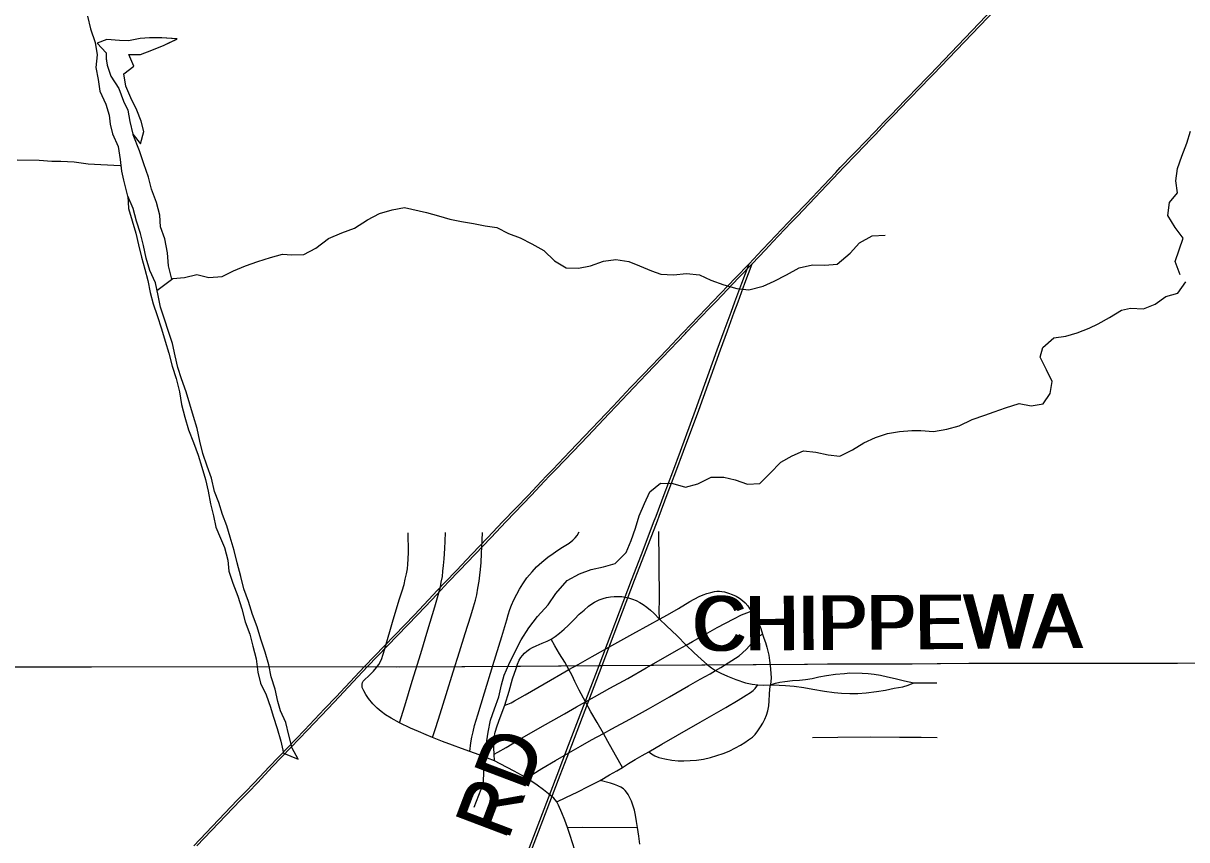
# Model space of a CAD drawing. Extents: x 0 to 34, y 0 to 22.
# Drawn here: x 21.074 to 22.288, y 9.409 to 10.261 of the extents above; entities that cross this region are included whole.
import ezdxf

# ---------------------------------------------------------------- set-up
doc = ezdxf.new("R2010")
doc.units = 0
for name, color, linetype in [('GM_X_City_Street', 7, 'Continuous'), ('GM_X_County_Road', 7, 'Continuous'), ('GM_X_County_Road_Text', 7, 'Continuous'), ('GM_X_Minor_Lake', 7, 'Continuous'), ('GM_X_Minor_River', 7, 'Continuous'), ('GM_X_US_Route', 7, 'Continuous')]:
    doc.layers.add(name, color=color, linetype=linetype)

msp = doc.modelspace()

# ---------------------------------------------------------------- linework, layer by layer
at = {"layer": 'GM_X_City_Street'}
for points in [[(21.4275, 9.5716), (21.4279, 9.5733), (21.4288, 9.5746), (21.4302, 9.5761), (21.4347, 9.5801), (21.4395, 9.585), (21.4427, 9.5888), (21.4452, 9.5921), (21.4478, 9.5971), (21.4497, 9.6028), (21.4519, 9.6107), (21.4594, 9.6362), (21.4663, 9.6593), (21.4693, 9.6688), (21.4713, 9.6755), (21.4726, 9.681), (21.4739, 9.6865), (21.4748, 9.6917), (21.4753, 9.6966), (21.4756, 9.702), (21.4758, 9.709), (21.4757, 9.7294)], [(21.4666, 9.5312), (21.472, 9.5487), (21.4799, 9.5744), (21.4889, 9.6034), (21.4963, 9.6282), (21.5034, 9.6521), (21.5068, 9.6642), (21.5092, 9.6729), (21.5102, 9.6778), (21.5113, 9.6837), (21.5119, 9.6894), (21.5125, 9.6951), (21.5132, 9.7021), (21.5139, 9.7129), (21.5142, 9.7205), (21.5144, 9.7296)], [(21.5011, 9.5159), (21.5044, 9.5264), (21.5089, 9.5406), (21.5151, 9.5605), (21.5226, 9.5844), (21.5292, 9.6053), (21.535, 9.6242), (21.5411, 9.6429), (21.5439, 9.6522), (21.5458, 9.659), (21.5471, 9.6648), (21.5484, 9.6716), (21.5496, 9.6789), (21.5505, 9.6852), (21.5511, 9.6911), (21.5517, 9.6982), (21.5522, 9.7076), (21.5528, 9.7216), (21.553, 9.7298)], [(21.5401, 9.5013), (21.5411, 9.5101), (21.5421, 9.5161), (21.5433, 9.5217), (21.5448, 9.5282), (21.5483, 9.5396), (21.5553, 9.5623), (21.564, 9.5909), (21.5733, 9.6212), (21.5784, 9.6385), (21.58, 9.6438), (21.5817, 9.6492), (21.5835, 9.6538), (21.5858, 9.6593), (21.5888, 9.6654), (21.5917, 9.6705), (21.5952, 9.676), (21.5995, 9.6823), (21.6048, 9.6887), (21.6096, 9.6937), (21.6149, 9.6988), (21.6212, 9.7038), (21.6269, 9.7079), (21.6316, 9.7111), (21.6367, 9.7143), (21.6436, 9.7187), (21.6472, 9.7216), (21.6497, 9.7241), (21.6518, 9.7267), (21.6541, 9.7302)], [(21.7377, 9.6394), (21.7375, 9.6488), (21.7376, 9.6585), (21.7375, 9.6989), (21.737, 9.7306)], [(21.5764, 9.5495), (21.5797, 9.5507), (21.5829, 9.5521), (21.5865, 9.5539), (21.5977, 9.5603), (21.6109, 9.568), (21.6239, 9.5756), (21.6349, 9.5819), (21.6432, 9.5866), (21.6528, 9.592), (21.6674, 9.6002), (21.6881, 9.6119), (21.7099, 9.6241), (21.7275, 9.6338), (21.7377, 9.6394), (21.7461, 9.6437), (21.7577, 9.6505), (21.7695, 9.6576), (21.7791, 9.6628), (21.7833, 9.6646), (21.787, 9.6659), (21.7912, 9.6672), (21.7952, 9.668), (21.7977, 9.6683), (21.8002, 9.6684), (21.8027, 9.6681), (21.8056, 9.6676), (21.8096, 9.6664), (21.8136, 9.6651), (21.8176, 9.6633), (21.8211, 9.6612), (21.8243, 9.6587), (21.827, 9.6562), (21.8297, 9.653), (21.8333, 9.6475)], [(21.6246, 9.6185), (21.629, 9.6212), (21.6335, 9.6246), (21.6382, 9.6289), (21.6425, 9.6328), (21.6492, 9.6394), (21.6541, 9.6443), (21.6591, 9.6488), (21.6637, 9.6527), (21.6661, 9.6546), (21.6699, 9.657), (21.6749, 9.6593), (21.6789, 9.6607), (21.6826, 9.6617), (21.6868, 9.6625), (21.6906, 9.6629), (21.6945, 9.663), (21.6983, 9.6628), (21.7018, 9.6623), (21.7053, 9.6615), (21.7097, 9.66), (21.7134, 9.6586), (21.7171, 9.6568), (21.7208, 9.6545), (21.7247, 9.6517), (21.7285, 9.6485), (21.7319, 9.6454), (21.7377, 9.6394), (21.745, 9.6323), (21.756, 9.6218), (21.7654, 9.6121), (21.7736, 9.6045), (21.7815, 9.5972), (21.7875, 9.5921), (21.792, 9.5886), (21.7963, 9.5856), (21.8018, 9.5829), (21.8087, 9.5798), (21.8172, 9.5764), (21.8276, 9.573), (21.8345, 9.5714), (21.8403, 9.5706), (21.8466, 9.5705), (21.8535, 9.5709)], [(21.5653, 9.4985), (21.569, 9.5004), (21.5778, 9.5055), (21.5922, 9.514), (21.6134, 9.5261), (21.6386, 9.5406), (21.6513, 9.5478), (21.6605, 9.553), (21.6698, 9.5584), (21.6861, 9.5673), (21.7046, 9.5775), (21.7239, 9.5885), (21.7464, 9.6012), (21.758, 9.6078), (21.7654, 9.6121), (21.7723, 9.6159), (21.7834, 9.6222), (21.798, 9.6304), (21.8153, 9.6397), (21.8231, 9.6436), (21.8288, 9.646), (21.8333, 9.6475)], [(21.8333, 9.6475), (21.8359, 9.6438), (21.8373, 9.6418), (21.839, 9.6386), (21.8405, 9.6359), (21.8419, 9.6329), (21.8433, 9.6294), (21.8451, 9.6237), (21.8466, 9.6195), (21.8482, 9.615), (21.8498, 9.6101), (21.8509, 9.6058), (21.8517, 9.6016), (21.8524, 9.5963), (21.853, 9.5912), (21.8538, 9.5825), (21.8541, 9.578), (21.8535, 9.5709)], [(21.5994, 9.4733), (21.6056, 9.4775), (21.615, 9.4834), (21.6293, 9.4919), (21.6409, 9.4985), (21.6554, 9.5067), (21.667, 9.5133), (21.6792, 9.52), (21.688, 9.5248), (21.7067, 9.5351), (21.7263, 9.5458), (21.7481, 9.5582), (21.7679, 9.5696), (21.7802, 9.5766), (21.7907, 9.5821), (21.7963, 9.5856), (21.8017, 9.589), (21.8094, 9.5938), (21.8169, 9.5985), (21.8208, 9.6011), (21.8244, 9.6043), (21.8285, 9.6081), (21.8337, 9.6139), (21.8374, 9.6182), (21.8398, 9.6203), (21.8422, 9.622), (21.8451, 9.6237)], [(21.5656, 9.4913), (21.5653, 9.4985), (21.5649, 9.5051), (21.5653, 9.5159), (21.5665, 9.5215), (21.5684, 9.5281), (21.5717, 9.5368), (21.5764, 9.5495), (21.5808, 9.5643), (21.5846, 9.5771), (21.5881, 9.5878), (21.5898, 9.5923), (21.5915, 9.5964), (21.5931, 9.5991), (21.5948, 9.6014), (21.5971, 9.6038), (21.5995, 9.6059), (21.6022, 9.608), (21.6053, 9.6098), (21.6091, 9.6116), (21.6153, 9.6142), (21.6205, 9.6163), (21.6246, 9.6185)], [(21.699, 9.4846), (21.6919, 9.4973), (21.6839, 9.5116), (21.6792, 9.52), (21.6728, 9.5314), (21.6663, 9.5427), (21.6605, 9.553), (21.6541, 9.5651), (21.6496, 9.5741), (21.6465, 9.5805), (21.6432, 9.5866), (21.6389, 9.5943), (21.6333, 9.6032), (21.6285, 9.6115), (21.6246, 9.6185)], [(21.8535, 9.5709), (21.8588, 9.5725), (21.8633, 9.5735), (21.8686, 9.5743), (21.8766, 9.5751), (21.8838, 9.5756), (21.8901, 9.5763), (21.8971, 9.5775), (21.9039, 9.5791), (21.9119, 9.5806), (21.9214, 9.5819), (21.9306, 9.5827), (21.9364, 9.5831), (21.9491, 9.5829), (21.9552, 9.5825), (21.9616, 9.5818), (21.9682, 9.5809), (21.9757, 9.5791), (21.9835, 9.5772), (21.9931, 9.575), (22.003, 9.5728)], [(21.6496, 9.3984), (21.6446, 9.4135), (21.6419, 9.422), (21.639, 9.4295), (21.6358, 9.4372), (21.6325, 9.4451), (21.6308, 9.4488), (21.6275, 9.4525), (21.6221, 9.457), (21.6167, 9.4613), (21.6101, 9.4662), (21.6045, 9.4698), (21.5994, 9.4733), (21.5938, 9.4766), (21.5862, 9.4807), (21.5788, 9.4846), (21.5717, 9.4885), (21.5656, 9.4913), (21.5583, 9.4943), (21.5496, 9.4977), (21.5401, 9.5013), (21.5312, 9.5044), (21.522, 9.5078), (21.5116, 9.5116), (21.5011, 9.5159), (21.4943, 9.5186), (21.4865, 9.5219), (21.4782, 9.5256), (21.4666, 9.5312), (21.458, 9.5358), (21.4521, 9.5395), (21.4476, 9.5429), (21.4432, 9.5465), (21.4389, 9.5508), (21.4342, 9.5565), (21.4315, 9.5605), (21.4293, 9.5644), (21.4278, 9.5678), (21.4275, 9.5698), (21.4275, 9.5716)], [(21.699, 9.4846), (21.7055, 9.4888), (21.7122, 9.4927), (21.7195, 9.497), (21.7266, 9.5009), (21.7403, 9.5088), (21.7566, 9.5182), (21.78, 9.5317), (21.807, 9.5471), (21.8197, 9.5547), (21.828, 9.5598), (21.8325, 9.5627), (21.8353, 9.5648), (21.8375, 9.567), (21.8403, 9.5706)], [(21.7266, 9.5009), (21.7295, 9.4987), (21.733, 9.4967), (21.737, 9.4951), (21.7434, 9.4934), (21.7505, 9.492), (21.7571, 9.4916), (21.7631, 9.4915), (21.7697, 9.4918), (21.7763, 9.4923), (21.7835, 9.4933), (21.7909, 9.4949), (21.7977, 9.497), (21.8042, 9.4992), (21.8103, 9.5017), (21.8169, 9.5049), (21.8222, 9.5078), (21.8269, 9.5107), (21.8307, 9.5133), (21.8346, 9.5163), (21.8374, 9.5188), (21.8402, 9.5226), (21.843, 9.5271), (21.8455, 9.5309), (21.8477, 9.5351), (21.8495, 9.539), (21.8508, 9.5437), (21.8517, 9.5489), (21.8522, 9.5539), (21.8526, 9.5609), (21.8529, 9.5662), (21.8535, 9.5709)], [(21.8535, 9.5709), (21.8626, 9.5705), (21.8692, 9.5701), (21.8783, 9.5692), (21.8882, 9.568), (21.8975, 9.5664), (21.9097, 9.5642), (21.92, 9.5627), (21.9275, 9.562), (21.9363, 9.5617), (21.9446, 9.5618), (21.9532, 9.5624), (21.9641, 9.5638), (21.9733, 9.5653), (21.9826, 9.5671), (21.9916, 9.5688), (21.9971, 9.5703), (22.003, 9.5728)], [(22.003, 9.5728), (22.0111, 9.5729), (22.027, 9.5728)], [(21.8973, 9.5159), (21.9238, 9.5161), (21.9579, 9.5164), (21.988, 9.5162), (22.0108, 9.516), (22.0272, 9.5159)], [(21.676, 9.471), (21.6856, 9.4767), (21.6932, 9.4812), (21.699, 9.4846)], [(21.6308, 9.4488), (21.6401, 9.4531), (21.6525, 9.4591), (21.6635, 9.4647), (21.676, 9.471)], [(21.7172, 9.4047), (21.7162, 9.4127), (21.7148, 9.4219), (21.7138, 9.428), (21.7126, 9.4347), (21.7115, 9.4401), (21.71, 9.4451), (21.7084, 9.4494), (21.7051, 9.4563), (21.7034, 9.4588), (21.7018, 9.4605), (21.7001, 9.4621), (21.6975, 9.4639), (21.6944, 9.4654), (21.6909, 9.4667), (21.6867, 9.4682), (21.676, 9.471)], [(21.6419, 9.422), (21.6574, 9.4221), (21.7148, 9.4219)]]:
    msp.add_lwpolyline(points, dxfattribs=at)
at = {"layer": 'GM_X_County_Road'}
for points in [[(21.5886, 9.3657), (21.631, 9.4766), (21.6429, 9.5077), (21.6747, 9.5909), (21.7086, 9.6798), (21.719, 9.7066), (21.7322, 9.7418), (21.7341, 9.7468), (21.7426, 9.7693), (21.7516, 9.7929), (21.7597, 9.8144), (21.7753, 9.8574), (21.798, 9.9202), (21.8053, 9.9401), (21.8124, 9.9595), (21.8164, 9.9703), (21.8236, 9.9898), (21.8311, 10.0101)], [(21.5919, 9.3657), (21.6342, 9.4766), (21.6462, 9.5077), (21.6779, 9.5909), (21.7118, 9.6798), (21.7222, 9.7066), (21.7355, 9.7418), (21.7373, 9.7468), (21.7458, 9.7693), (21.7548, 9.7929), (21.7629, 9.8144), (21.7786, 9.8574), (21.8012, 9.9202), (21.8086, 9.9401), (21.8157, 9.9595), (21.8197, 9.9703), (21.8269, 9.9898), (21.8344, 10.0101)], [(20.5462, 9.5901), (20.5479, 9.5895), (20.5507, 9.589), (20.5541, 9.5887), (20.5643, 9.5886), (20.5795, 9.5883), (20.6219, 9.5884), (20.879, 9.589), (20.9124, 9.5892), (20.9455, 9.5893), (20.9787, 9.5894), (21.0336, 9.5895), (21.1421, 9.5894), (21.43, 9.5899)], [(20.5495, 9.5901), (20.5512, 9.5895), (20.554, 9.589), (20.5574, 9.5887), (20.5676, 9.5886), (20.5828, 9.5883), (20.6252, 9.5884), (20.8823, 9.589), (20.9156, 9.5892), (20.9488, 9.5893), (20.9819, 9.5894), (21.0369, 9.5895), (21.1453, 9.5894), (21.4332, 9.5899)], [(21.43, 9.5899), (21.4637, 9.5896), (21.5315, 9.5898), (21.5895, 9.5902), (21.6747, 9.5909), (21.8888, 9.5924), (21.9129, 9.5925), (21.9705, 9.5926), (21.9978, 9.5928), (22.0275, 9.5929), (22.0602, 9.5932), (22.1049, 9.5934), (22.1549, 9.5932), (22.2459, 9.5934), (22.2747, 9.5935), (22.3004, 9.5936), (22.3176, 9.5938), (22.3801, 9.5944), (22.3988, 9.5947), (22.4694, 9.5948), (22.5401, 9.5938), (22.5966, 9.5931), (22.6135, 9.5929)], [(21.4332, 9.5899), (21.467, 9.5896), (21.5348, 9.5898), (21.5928, 9.5902), (21.6779, 9.5909), (21.892, 9.5924), (21.9161, 9.5925), (21.9738, 9.5926), (22.0011, 9.5928), (22.0308, 9.5929), (22.0634, 9.5932), (22.1082, 9.5934), (22.1582, 9.5932), (22.2491, 9.5934), (22.278, 9.5935), (22.3037, 9.5936)]]:
    msp.add_lwpolyline(points, dxfattribs=at)
at = {"layer": 'GM_X_Minor_Lake'}
for points in [[(21.2348, 10.2446), (21.2186, 10.2458), (21.2057, 10.2458), (21.1962, 10.245), (21.184, 10.2427), (21.1745, 10.243), (21.1615, 10.2441), (21.1513, 10.2403), (21.1605, 10.2301), (21.1607, 10.224)], [(21.2338, 10.2447), (21.2186, 10.2458), (21.2057, 10.2458), (21.1962, 10.245), (21.184, 10.2427), (21.1745, 10.243), (21.1615, 10.2441), (21.1513, 10.2403), (21.1605, 10.2301), (21.1607, 10.2229)], [(21.1607, 10.224), (21.1616, 10.2172), (21.1655, 10.2058), (21.1739, 10.1929), (21.1789, 10.1796), (21.1831, 10.1701), (21.1855, 10.1584), (21.1886, 10.1451), (21.1966, 10.1352), (21.2, 10.1481), (21.1973, 10.1588), (21.1926, 10.1702), (21.1865, 10.1831), (21.1811, 10.1952), (21.1792, 10.2081), (21.1894, 10.2161), (21.1844, 10.2283), (21.1966, 10.2283), (21.2084, 10.2329), (21.2213, 10.2382), (21.2348, 10.2446)], [(21.1607, 10.2237), (21.1616, 10.2172), (21.1655, 10.2058), (21.1739, 10.1929), (21.1789, 10.1796), (21.1831, 10.1701), (21.1855, 10.1584), (21.1886, 10.1451), (21.1966, 10.1352), (21.2, 10.1481), (21.1973, 10.1588), (21.1926, 10.1702), (21.1865, 10.1831), (21.1811, 10.1952), (21.1792, 10.2081), (21.1894, 10.2161), (21.1844, 10.2283), (21.1966, 10.2283), (21.2084, 10.2329), (21.2213, 10.2382), (21.2342, 10.2443)]]:
    msp.add_lwpolyline(points, dxfattribs=at)
at = {"layer": 'GM_X_Minor_River'}
msp.add_line((21.3457, 9.4993), (21.3608, 9.4933), dxfattribs=at)
for points in [[(21.1412, 10.2684), (21.1444, 10.255), (21.1491, 10.2409), (21.1512, 10.2279), (21.1498, 10.2146), (21.1523, 10.2021), (21.1539, 10.1899), (21.1602, 10.1765), (21.1638, 10.165), (21.1648, 10.1555), (21.1673, 10.1456), (21.1731, 10.1325), (21.1752, 10.1188), (21.1768, 10.1066), (21.1786, 10.0971), (21.1831, 10.0793)], [(21.2293, 9.994), (21.2257, 10.0077), (21.2245, 10.0214), (21.2217, 10.0359), (21.2173, 10.0485), (21.2168, 10.0607), (21.2132, 10.0741), (21.2081, 10.0878), (21.2049, 10.1004), (21.1998, 10.1142), (21.1955, 10.1279), (21.1888, 10.1446)], [(22.2806, 9.9985), (22.2755, 10.0123), (22.2796, 10.0244), (22.284, 10.0368), (22.2754, 10.048), (22.268, 10.0603), (22.2698, 10.074), (22.2779, 10.0841), (22.2762, 10.0966), (22.278, 10.1095), (22.2824, 10.1224), (22.2876, 10.1359), (22.2916, 10.1484)], [(21.0679, 10.1185), (21.0907, 10.1181), (21.104, 10.1171), (21.1135, 10.1169), (21.1272, 10.1163), (21.142, 10.1141), (21.1751, 10.1124)], [(21.3608, 9.4933), (21.3547, 9.5047), (21.3512, 9.5184), (21.348, 9.5314), (21.3425, 9.5436), (21.3396, 9.5532), (21.3368, 9.5661), (21.3328, 9.5791), (21.3304, 9.5917), (21.3264, 9.6047), (21.3221, 9.6185), (21.3181, 9.6314), (21.3134, 9.6441), (21.3091, 9.6578), (21.3044, 9.6708), (21.3012, 9.6838), (21.2972, 9.6979), (21.294, 9.7109), (21.2901, 9.7247), (21.2865, 9.7365), (21.2821, 9.7484), (21.2781, 9.761), (21.2738, 9.7724), (21.2706, 9.7862), (21.2659, 9.7988), (21.2615, 9.8122), (21.2583, 9.8251), (21.2555, 9.8381), (21.2519, 9.8507), (21.248, 9.8637), (21.244, 9.8763), (21.2393, 9.8901), (21.2353, 9.9019), (21.2325, 9.9141), (21.2297, 9.9267), (21.2257, 9.9393), (21.2214, 9.9523), (21.2174, 9.9646), (21.2149, 9.9768), (21.2121, 9.9901), (21.2063, 10.0031), (21.2023, 10.0157), (21.1995, 10.0291), (21.1963, 10.0417), (21.1923, 10.0543), (21.1887, 10.0677), (21.1832, 10.0807), (21.1838, 10.0677), (21.1877, 10.0548), (21.1917, 10.0421), (21.1945, 10.0299), (21.1974, 10.017), (21.2009, 10.0044), (21.2042, 9.9925), (21.2066, 9.98), (21.2098, 9.9681), (21.2138, 9.9559), (21.2185, 9.9421), (21.2221, 9.9291), (21.2261, 9.9169), (21.2296, 9.9032), (21.2336, 9.8902), (21.2372, 9.8764), (21.2392, 9.8631), (21.2428, 9.8501), (21.2467, 9.8368), (21.2518, 9.8237), (21.2566, 9.8104), (21.2605, 9.7978), (21.2641, 9.7848), (21.2669, 9.7729), (21.2694, 9.7596), (21.2726, 9.747), (21.275, 9.7352), (21.2798, 9.7237), (21.2842, 9.7141), (21.2874, 9.7008), (21.2887, 9.6893), (21.2927, 9.6767), (21.2981, 9.6633), (21.3021, 9.65), (21.3057, 9.6366), (21.3104, 9.6236), (21.3136, 9.611), (21.3172, 9.5977), (21.3188, 9.5839), (21.3217, 9.5725), (21.3276, 9.5602), (21.3319, 9.5476), (21.3348, 9.5381), (21.3391, 9.5251), (21.3427, 9.5121), (21.3457, 9.4993)], [(21.2136, 9.9822), (21.2301, 9.9947), (21.2423, 9.9956), (21.2553, 9.9988), (21.2678, 9.9956), (21.2815, 9.9968), (21.2934, 10.0027), (21.306, 10.0078), (21.3187, 10.0125), (21.332, 10.0164), (21.3447, 10.02), (21.3542, 10.0195), (21.3667, 10.0196), (21.3794, 10.0262), (21.3925, 10.0362), (21.4063, 10.0424), (21.4197, 10.0471), (21.4332, 10.056), (21.4458, 10.0626), (21.4588, 10.0662), (21.4718, 10.0686), (21.4946, 10.0636), (21.5071, 10.06), (21.5192, 10.0567), (21.5313, 10.0542), (21.5438, 10.0521), (21.556, 10.0496), (21.5681, 10.0479), (21.5802, 10.0416), (21.5926, 10.0372), (21.6047, 10.0309), (21.6171, 10.0238), (21.6284, 10.013), (21.6404, 10.0059), (21.6533, 10.0053), (21.6659, 10.0077), (21.6794, 10.0128), (21.6923, 10.0145), (21.7056, 10.0123), (21.7169, 10.008), (21.7294, 10.0028), (21.7392, 9.9992), (21.7522, 9.9986), (21.7659, 9.9999), (21.7795, 9.9985), (21.7912, 9.9929), (21.8049, 9.9881), (21.8185, 9.9841), (21.831, 9.9827), (21.8459, 9.9866), (21.8574, 9.9917), (21.8701, 9.9983), (21.8835, 10.0057), (21.8973, 10.0089), (21.9102, 10.0086), (21.9232, 10.0095), (21.9367, 10.0211), (21.9464, 10.0319), (21.9595, 10.0393), (21.9732, 10.0398)], [(21.5446, 9.443), (21.5542, 9.468), (21.5545, 9.4809), (21.5551, 9.4942), (21.5568, 9.5078), (21.559, 9.5215), (21.5615, 9.534), (21.5655, 9.5457), (21.5703, 9.5581), (21.5731, 9.5706), (21.5756, 9.5808), (21.5807, 9.5921), (21.5867, 9.6049), (21.5934, 9.6177), (21.6016, 9.6301), (21.6105, 9.6421), (21.6218, 9.6541), (21.6296, 9.6661), (21.6416, 9.6795), (21.6543, 9.6865), (21.6665, 9.6909), (21.6795, 9.6937), (21.6914, 9.6973), (21.703, 9.7088), (21.7082, 9.7213), (21.7126, 9.7341), (21.7166, 9.747), (21.7221, 9.7598), (21.7277, 9.7722), (21.7389, 9.7811), (21.7518, 9.7809), (21.7647, 9.7769), (21.7777, 9.7804), (21.7915, 9.7874), (21.8048, 9.7875), (21.8165, 9.7847), (21.8294, 9.7802), (21.8424, 9.7808), (21.8528, 9.7912), (21.8644, 9.8032), (21.876, 9.8098), (21.8878, 9.8149), (21.9008, 9.8135), (21.9136, 9.8106), (21.9258, 9.8093), (21.9392, 9.8159), (21.9508, 9.8233), (21.963, 9.8287), (21.9757, 9.8331), (21.9879, 9.8351), (22.0008, 9.836), (22.0103, 9.8359), (22.0236, 9.8352), (22.0374, 9.8373), (22.0504, 9.8408), (22.0638, 9.8474), (22.0772, 9.8521), (22.0868, 9.8554), (22.0986, 9.8597), (22.1128, 9.8644), (22.1253, 9.8619), (22.1379, 9.864), (22.1453, 9.8745), (22.1474, 9.8873), (22.1412, 9.8992), (22.1349, 9.9126), (22.1374, 9.9225), (22.149, 9.9329), (22.1616, 9.9346), (22.1734, 9.9378), (22.1857, 9.9429), (22.1953, 9.9473), (22.2072, 9.9539), (22.2195, 9.9616), (22.229, 9.9637), (22.2424, 9.9631), (22.2546, 9.9678), (22.2658, 9.976), (22.2784, 9.9792), (22.2866, 9.9912)]]:
    msp.add_lwpolyline(points, dxfattribs=at)
at = {"layer": 'GM_X_US_Route'}
for points in [[(21.252, 9.4029), (21.2973, 9.4503), (21.3053, 9.4584), (21.3155, 9.469), (21.3307, 9.4851), (21.3501, 9.5055), (21.3674, 9.5235), (21.3885, 9.5458), (21.4008, 9.5586), (21.4049, 9.563), (21.43, 9.5899), (21.4822, 9.6437), (21.497, 9.6594), (21.5063, 9.6694), (21.5142, 9.6777), (21.526, 9.6901), (21.5421, 9.7072), (21.5584, 9.7242), (21.5745, 9.741), (21.6011, 9.7687), (21.6143, 9.7827), (21.6203, 9.789), (21.6264, 9.7954), (21.6444, 9.8142), (21.6596, 9.8301), (21.6821, 9.8538), (21.6894, 9.8615), (21.7076, 9.8808), (21.7209, 9.8949), (21.7456, 9.9207), (21.7615, 9.9373), (21.7624, 9.9382), (21.7864, 9.9634), (21.7938, 9.9711), (21.817, 9.9953), (21.8311, 10.0101), (21.8449, 10.0247), (21.8528, 10.033), (21.8586, 10.0392), (21.8719, 10.0531), (21.8782, 10.0597), (21.8907, 10.0726), (21.909, 10.0919), (21.9217, 10.1053), (21.9263, 10.1104), (21.9399, 10.1244), (21.9554, 10.1404), (21.96, 10.1452), (21.9629, 10.1483), (21.9718, 10.1576), (21.9789, 10.165), (21.9939, 10.1806), (21.9959, 10.1826), (21.9995, 10.1864), (22.0034, 10.1904), (22.0199, 10.2075), (22.0927, 10.2836)], [(21.2553, 9.4029), (21.3006, 9.4503), (21.3086, 9.4584), (21.3188, 9.469), (21.3339, 9.4851), (21.3534, 9.5055), (21.3707, 9.5235), (21.3917, 9.5458), (21.4041, 9.5586), (21.4081, 9.563), (21.4332, 9.5899), (21.4855, 9.6437), (21.5002, 9.6594), (21.5096, 9.6694), (21.5174, 9.6777), (21.5293, 9.6901), (21.5454, 9.7072), (21.5617, 9.7242), (21.5777, 9.741), (21.6044, 9.7687), (21.6175, 9.7827), (21.6235, 9.789), (21.6297, 9.7954), (21.6476, 9.8142), (21.6629, 9.8301), (21.6854, 9.8538), (21.6927, 9.8615), (21.7109, 9.8808), (21.7241, 9.8949), (21.7489, 9.9207), (21.7648, 9.9373), (21.7656, 9.9382), (21.7897, 9.9634), (21.7971, 9.9711), (21.8203, 9.9953), (21.8344, 10.0101), (21.8482, 10.0247), (21.856, 10.033), (21.8619, 10.0392), (21.8752, 10.0531), (21.8815, 10.0597), (21.894, 10.0726), (21.9122, 10.0919), (21.9249, 10.1053), (21.9296, 10.1104), (21.9431, 10.1244), (21.9586, 10.1404), (21.9632, 10.1452), (21.9662, 10.1483), (21.975, 10.1576), (21.9821, 10.165), (21.9972, 10.1806), (21.9991, 10.1826), (22.0027, 10.1864), (22.0066, 10.1904), (22.0231, 10.2075), (22.096, 10.2836)]]:
    msp.add_lwpolyline(points, dxfattribs=at)

# ---------------------------------------------------------------- texts
at = {"layer": 'GM_X_County_Road_Text'}
for s, rotation, p in [('CHIPPEWA', 0.4033, (21.7713, 9.6062)), ('CHIPPEWA', 0.4033, (21.7746, 9.6062)), ('RD', 69.2119, (21.5764, 9.4076)), ('RD', 69.2119, (21.5797, 9.4076))]:
    msp.add_text(s, height=0.05682, rotation=rotation, dxfattribs=at).set_placement(p)

doc.saveas('drawing.dxf')
